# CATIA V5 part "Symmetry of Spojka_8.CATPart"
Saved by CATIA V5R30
Part number: Symmetry of Spojka_8
Bounding box of the stored display mesh (mm): x -8.66 to 8.66, y -7.5 to 7.5, z -9 to 17
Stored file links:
  E:\Bakalarka\Model\Forma_v7\Symmetry of Spojka_8.CATPart
  E:\Bakalarka\Model\Forma_v7\Spojka_1.CATPart
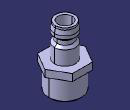
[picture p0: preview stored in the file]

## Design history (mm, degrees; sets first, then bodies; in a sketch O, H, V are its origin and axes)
Body1 (main body)
  Body2 "Body from original PartBody"
    Solid1: linked copy from another document
  Assemble1: tool Body2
